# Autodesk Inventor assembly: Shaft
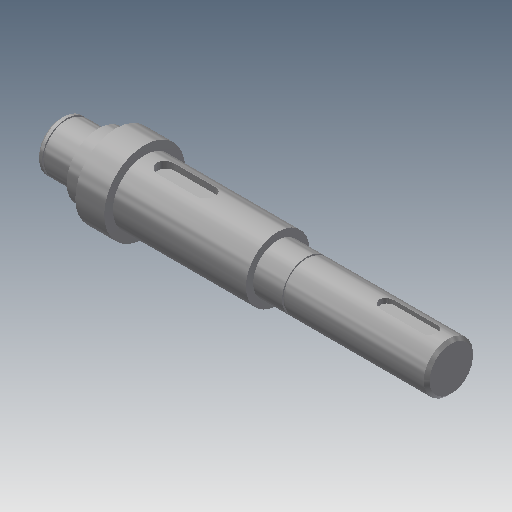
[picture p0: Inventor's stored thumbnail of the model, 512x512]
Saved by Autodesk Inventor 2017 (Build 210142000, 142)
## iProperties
Created: 2019-02
Part Number: Shaft
Document SubType Name: Assembly
Designer: user
ClientObjectVersion: 1
Author: user
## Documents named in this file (2)
- C:\Users\user\Documents\EIA\Cursos\Diseño asistido por computador\Clase 7 Dynamic simulation\Ensamble reductor de velocidad\Ensamble\Design Accelerator\Shaft1.iam
- C:\Users\user\Documents\EIA\Cursos\Diseño asistido por computador\Clase 7 Dynamic simulation\Ensamble reductor de velocidad\Ensamble\Design Accelerator\Shaft1.ipt
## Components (1 placed, 1 different names)
1. Shaft:1
